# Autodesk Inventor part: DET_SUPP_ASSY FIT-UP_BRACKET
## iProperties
Shininess: 64.0
Length Units: 11272
Angle Units: 11279
Time Units: 11290
Mass Units: 11286
Length Display Precision: 3
Angle Display Precision: 2
Compacted: True
Part Number: DET_SUPP_ASSY FIT-UP_BRACKET
Document SubType Name: Modeling
Created: 2004-08
Designer: John Blackburn
Manufacturer: Standard
Standards Organization: Custom
Material: Aluminum-6061
Density: 0.0
Volumn: 0.0
Area: 0.0
PropertySet Name: Model Information
Control State: 0
Master: False
Checked Out: False
Author: John Blackburn
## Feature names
1. ExtrusionMidplane1
